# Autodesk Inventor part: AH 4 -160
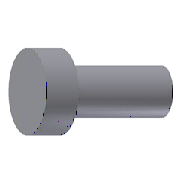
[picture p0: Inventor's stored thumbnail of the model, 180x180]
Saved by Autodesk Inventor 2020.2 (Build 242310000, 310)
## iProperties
Manager: www.cadconsulting.pl
Company: Fabian Stasiak CAD Consulting
Created: 2014-02
Part Number: AH 4 -160
Material: DIN 1.2210
Description: Kołki wypychacza – hartowane
Document SubType Name: Modeling
Standard: DIN 1530/ISO 6751
Designer: F.Stasiak
Standard Revision: 1
Manufacturer: DME
Language: pl-PL
Size Designation: 4 -160
Categories: <MemberInstance><Categories><Category DisplayName="Forma wtryskowa" InternalName="349578f2-f4d4-4954-8c09-8e99297a61c0" Mnemonic="MOLD"><Category DisplayName="K
Mass: 0.191827 g
Surface Area: 2.51725 cm^2
Volume: 0.191827 cm^3
Density: 7.85 g/cm^3
Appearance: Aluminium - ciemne
Catalog Web Link: www.expertbooks.pl
IsCustomPart: 1
Author: F.Stasiak
Subject: Zbiór ćwiczeń. Autodesk Inventor 2020. Kurs Professional
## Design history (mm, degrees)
workplane "Work Plane1"
sketch "Sketch2"
  geometry: L1 (4, -1.5)-(-4, -1.5) reference; L2 (-4, -1.5)-(-4, 1.5) reference; 4 further points
  constraints: 2 midpoint, 1 horizontal alignment, 1 vertical alignment
hole "Otwór ustalający" sketch "Sketch2" at (0, 0) diameter "d44" = 0.55 (derived); stored, may be unused: countersink angle "d48" = 90 deg, drill point angle "d50" = 118 deg; dims "d45" = 6, "d46" = 4, "d47" = 2, "d49" = 0.825 (derived)
sketch "Sketch3"
  geometry: L1 (-2.3, 3.273)-(-2.3, -3.273); A1 r 4 centre (0, 0) between (-2.3, 3.273) and (-2.3, -3.273) reference; 1 further point
  constraints: 2 end point, 2 point on circle, 1 vertical
  dimensions: "d55" = 2.3 distance from line of point (0, 0) L1 (derived)
extrude "Płaszczyzna ustalająca" cut sketch "Sketch3" distance "d42" = 3.3 (derived); taper "d43" = 0 deg
feature "Rzeźbienie1"
node "Płaszczyzna konstrukcyjna2"
body "Solid1"
revolve "Obrót1" stored, may be unused: angle "d11" = 90 deg
fillet "Zaokrąglenie1" dims "d29" = 0.3 (derived)
sketch "Sketch1"
  geometry: L1 (0, 4)-(3, 4); L2 (0, 0)-(0, 4); L3 (3, 2)-(160, 2); L4 (160, 2)-(160, 0); L5 (0, 0)-(160, 0); L6 (3, 4)-(3, 2); 2 further points
  constraints: 12 end point, 4 point on line, 2 horizontal, 2 perpendicular, 1 coincident
  dimensions: "d6" = 3 distance of L1.start L1.end (derived); "d9" = 160 distance between parallel lines of L4 L2 (derived); "d10" = 8 diameter of L1 L5 (derived); "d13" = 4 diameter of L3 L5 (derived)
node "Projected Loop1"
feature "Powierzchnia1"
body "Srf1"
other parameters: "d15" = 0, "d24" = 0, "P" = 4 [user parameter], "T_" = 3 [user parameter], "H_" = 8 [user parameter], "R" = 0.3 [user parameter], "Anti_Rotary_P" = 2.3 [user parameter], "Anti_Rotary_D" = 0.55 [user parameter], "d51" = 0, "d54" = 0, "d56" = 0, "d57" = 0
